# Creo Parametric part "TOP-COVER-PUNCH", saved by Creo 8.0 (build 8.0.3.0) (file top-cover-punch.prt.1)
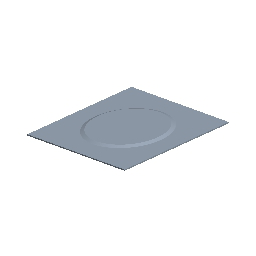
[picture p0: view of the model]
Units: millimeter Newton Second (mmNs); MM, TONNE, SECS

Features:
  1. datum plane "RIGHT"
  2. datum plane "TOP"
  3. datum plane "FRONT"
  4. coordinate system
  5. protrusion
  6. protrusion
  7. round
  8. round

Layers: 0_ALL_AXIS, 0_ALL_CSYS, 0_ALL_CURVE, 0_ALL_PLANE, 0_ALL_POINT, 0_ALL_SURFACE

Surfaces: 7 plane, 4 torus, 2 cone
